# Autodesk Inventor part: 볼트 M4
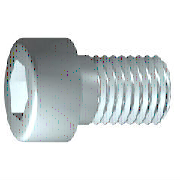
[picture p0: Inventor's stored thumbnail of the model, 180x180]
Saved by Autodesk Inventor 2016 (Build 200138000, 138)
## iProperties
IsCustomPart: 0
Created: 2015-12
Part Number: 볼트 M4
Material: 강철, 연강
Description: 6각머리 태핑 나사
Document SubType Name: Modeling
Standard: KS B 1003
Designer: mdu
Standards Organization: KS
Language: ko-KR
Size Designation: M 4 x 12
Categories: <MemberInstance><Categories><Category DisplayName="조임쇠" InternalName="e4da775c-781d-43d5-af7c-5136215cf5a6" Mnemonic="FSTN"><Category DisplayName="볼트" InternalN
Density: 7.86 g/cm^3
Appearance: 강철
Mass: 2.23465 g
Surface Area: 3.30853 cm^2
Volume: 0.284306 cm^3
Author: mdu
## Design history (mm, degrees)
sketch "스케치1"
  geometry: L1 (-1, 0)-(12, 0); L2 (12, 0)-(12, 2); L3 (12, 2)-(1.75, 2); L4 (1.75, 2)-(1.32, 2); L5 (1.32, 2)-(0, 2); L6 (0, 2)-(0, 3.5); L7 (0, 3.5)-(-4, 3.5); L8 (-4, 3.5)-(-4, 1.732); L9 (-4, 1.732)-(-2, 1.732); L10 (-2, 1.732)-(-1, 0); L11 (-7.2, 0)-(15.2, 0) reference; L12 (0, -0.7)-(0, 4.2) reference; L13 (1.75, 2)-(0, 2)
  constraints: 22 end point, 6 parallel, 2 collinear, 2 perpendicular, 1 horizontal, 1 point on line
  dimensions: "d1" = 10.25 distance from line of L3.end L2 (= GEL); "d2" = 0.42952 distance of L4.end L3.end (computed from GAL); "d3" = 4 distance between parallel lines of L8 L6 (= KOH); "d4" = 2 distance of L8.end L9.end (= INTI); "d5" = 60 deg angle of L10 L1; "d6" = 4 diameter of L3 L1 (= GD); "d7" = 4 diameter of L5 L1 (= BDM); "d8" = 3.4641 diameter of L9 L1 (= 1.1547 x SW); "d9" = 7 diameter of L7 L1 (= KOD); "d26" = 12 distance between parallel lines of L12 L2 (= NLG)
revolve "본체" sketch "스케치1" stored, may be unused: angle "d10" = 90 deg
sketch "스케치2"
  geometry: L1 (0, -4.9)-(0, 4.9) reference; L2 (-4.9, 0)-(4.9, 0) reference; L3 (1.732, 0)-(0.866, -1.5); L4 (0.866, -1.5)-(-0.866, -1.5); L5 (-0.866, -1.5)-(-1.732, 0); L6 (-1.732, 0)-(-0.866, 1.5); L7 (-0.866, 1.5)-(0.866, 1.5); L8 (0.866, 1.5)-(1.732, 0); 2 further points
  constraints: 12 end point, 1 coincident, 1 horizontal alignment, 1 point on line, 12 other
extrude "슬롯" join sketch "스케치2" stored distance "d11" = 10; taper "d12" = 0 deg
workplane "Work Plane1"
fillet "Fillet2" dims "d30" = 0.1 (= R)
body "Solid1"
fillet "모깎기1" dims "d17" = 0.4 (= RR)
feature "스레드" dims "d13" = 10.25 (= GEL), "d14" = 0
chamfer "모따기1" distance "d15" = 0.42941 (= -0.5 x SPD + 0.5 x GD); stored, may be unused: second distance "d16" = 0.42941 (= GUL), angle "d27" = 45 deg
other parameters: "GD" = 4 (= NND) [user parameter; used in 2 equation terms], "NLG" = 12 [user parameter; used in 1 equation term], "GEL" = 10.25 [user parameter; used in 2 equation terms], "KOD" = 7 [user parameter; used in 1 equation term], "KOH" = 4 [user parameter; used in 1 equation term], "INTI" = 2 [user parameter; used in 1 equation term], "GAL" = 0.42941 (= 0.61345 x PTC) [user parameter; used in 1 equation term], "GUL" = 0.42941 (= 0.61345 x PTC) [user parameter; used in 1 equation term], "BDM" = 4 (= NND) [user parameter; used in 1 equation term], "SW" = 3 [user parameter; used in 2 equation terms], "RR" = 0.4 [user parameter; used in 1 equation term], "SPD" = 3.14117 (= NND - 1.2269 x PTC) [user parameter; used in 1 equation term], "d19" = 0, "d28" = 0, "d29" = 0, "R" = 0.1 [user parameter; used in 1 equation term], "PHH" = 0.2 [user parameter], "GD1" = 3.14117 (= THREADDIA - 1.2269 x PTC) [user parameter], "THREADDIA" = 4 [user parameter; used in 1 equation term], "FAWI" = 45 deg [user parameter], "TPU" = 14.28571 (computed from PTC) [user parameter], "PTC" = 0.7 [user parameter; used in 5 equation terms], "NND" = 4 [user parameter; used in 3 equation terms], "TOA" = 30 deg [user parameter], "E0" = 3.465 (= 1.155 x SW) [user parameter]
